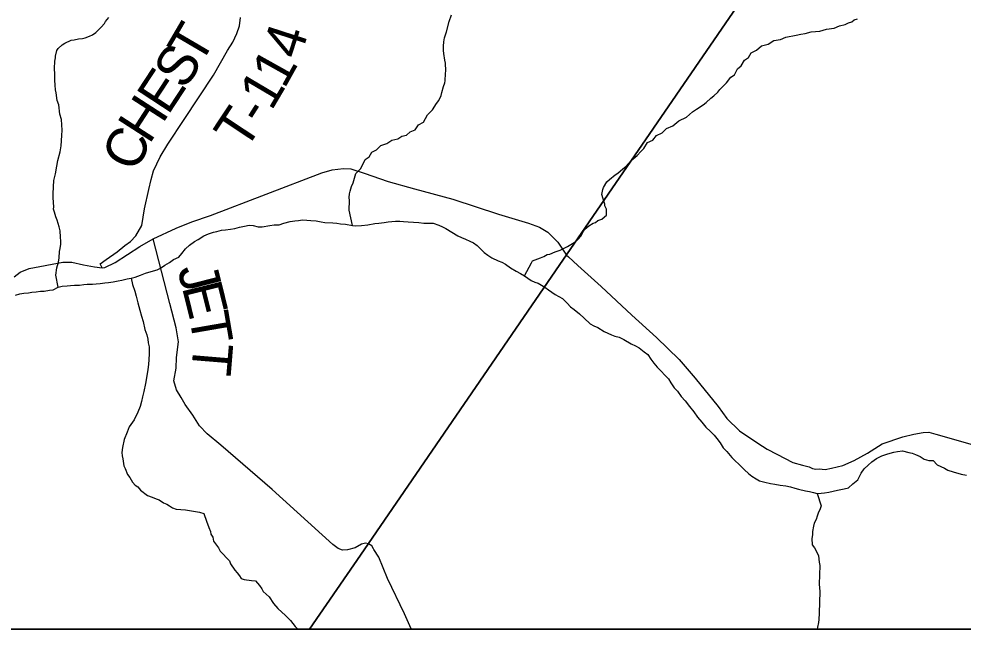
# Model space of a CAD drawing. Extents: x 0 to 39.3, y -3.9 to 22.
# Drawn here: x 3.453 to 4.806, y 13.9 to 14.774 of the extents above; entities that cross this region are included whole.
import ezdxf

# ---------------------------------------------------------------- set-up
doc = ezdxf.new("R2010")
doc.units = 0
for name, color, linetype in [('GM_X_Corporation', 7, 'Continuous'), ('GM_X_County_Road', 7, 'Continuous'), ('GM_X_County_Road_Text', 7, 'Continuous'), ('GM_X_Minor_River', 7, 'Continuous'), ('GM_X_Township_Road', 7, 'Continuous'), ('GM_X_Township_Road_Text', 7, 'Continuous'), ('SH_Data', 7, 'Continuous')]:
    doc.layers.add(name, color=color, linetype=linetype)

msp = doc.modelspace()

# ---------------------------------------------------------------- linework, layer by layer
at = {"layer": 'GM_X_Corporation'}
for points in [[(6.2667, 17.3782), (6.0256, 17.0319), (5.8398, 16.7652), (5.744, 16.6289), (5.7424, 16.6266), (5.2028, 15.8376), (5.0728, 15.652), (4.2376, 14.4362), (4.2334, 14.4302), (3.9536, 14.0228), (3.9474, 14.0138), (3.8692, 13.9), (7.894, 13.9)], [(1.9, 13.9), (3.8692, 13.9), (3.9474, 14.0138), (3.9536, 14.0228), (4.2334, 14.4302), (4.2376, 14.4362), (5.0728, 15.652)]]:
    msp.add_lwpolyline(points, dxfattribs=at)
at = {"layer": 'GM_X_County_Road'}
for points in [[(3.645, 14.4589), (3.6782, 14.4744), (3.7004, 14.4833), (3.7272, 14.4926), (3.887, 14.5537), (3.9018, 14.558), (3.9181, 14.5597), (3.9285, 14.5594), (3.9478, 14.553), (3.9821, 14.5412), (4.0196, 14.5307), (4.0745, 14.5158), (4.1401, 14.4943), (4.1829, 14.4816), (4.1988, 14.476), (4.2108, 14.4685), (4.2253, 14.4544), (4.2378, 14.4357), (4.2406, 14.4331)], [(3.572, 14.4178), (3.5761, 14.418), (3.5907, 14.4252), (3.6262, 14.4482), (3.645, 14.4589)], [(3.9611, 14.0149), (3.9585, 14.0191), (3.9538, 14.0222), (3.9494, 14.023), (3.9438, 14.0215), (3.9347, 14.0165), (3.9239, 14.0136), (3.9164, 14.013), (3.9101, 14.0156), (3.9025, 14.0212), (3.8156, 14.1), (3.7424, 14.1635), (3.7226, 14.1797), (3.7117, 14.191), (3.7021, 14.2066), (3.6911, 14.2218), (3.6855, 14.2317), (3.6788, 14.2426), (3.6749, 14.2557), (3.6781, 14.2738), (3.6788, 14.2889), (3.6813, 14.3116), (3.6781, 14.3314), (3.6689, 14.3664), (3.645, 14.4589)], [(3.4461, 14.4047), (3.4546, 14.4114), (3.4674, 14.4164), (3.5156, 14.4258), (3.5288, 14.4255), (3.5454, 14.4221), (3.5613, 14.4189), (3.572, 14.4178)], [(4.2406, 14.4331), (4.2539, 14.4208), (4.2871, 14.3908), (4.3313, 14.3498), (4.3667, 14.3179), (4.3992, 14.2861), (4.4218, 14.2593), (4.4547, 14.219), (4.4672, 14.2016), (4.4857, 14.184), (4.512, 14.1666), (4.5252, 14.1579), (4.5392, 14.1504), (4.5621, 14.1388), (4.576, 14.1351), (4.5852, 14.1323), (4.5903, 14.1303), (4.5949, 14.1289), (4.5995, 14.1294), (4.6083, 14.1287), (4.6175, 14.1305), (4.6334, 14.1342), (4.6499, 14.1415), (4.6691, 14.1522), (4.69, 14.1652), (4.7195, 14.1753), (4.7351, 14.1794), (4.7485, 14.1818), (4.7569, 14.1821), (4.7667, 14.1795), (4.7922, 14.172), (4.8202, 14.1642)], [(4.0152, 13.9), (4.015, 13.9005), (4.0055, 13.9219), (3.981, 13.9726), (3.9687, 14.003), (3.9616, 14.0141), (3.9611, 14.0149)]]:
    msp.add_lwpolyline(points, dxfattribs=at)
at = {"layer": 'GM_X_Minor_River'}
for points in [[(3.9309, 14.4782), (3.9259, 14.5003), (3.9265, 14.5139), (3.9262, 14.5181), (3.9267, 14.5238), (3.9275, 14.5276), (3.9296, 14.5341), (3.9316, 14.5394), (3.9356, 14.5526), (3.943, 14.5601), (3.9489, 14.5726), (3.9547, 14.5766), (3.9586, 14.5834), (3.9652, 14.5867), (3.9714, 14.5927), (3.9802, 14.5956), (3.9871, 14.6005), (3.9959, 14.6022), (4.0017, 14.6063), (4.0085, 14.6077), (4.0136, 14.6122), (4.0205, 14.6151), (4.0256, 14.6223), (4.0325, 14.6263), (4.0384, 14.6369), (4.0454, 14.644), (4.0512, 14.653), (4.0544, 14.6575), (4.0579, 14.6643), (4.0591, 14.6689), (4.0612, 14.6772), (4.0632, 14.6825), (4.0636, 14.6856), (4.0642, 14.6958), (4.0646, 14.6996), (4.0641, 14.7107), (4.063, 14.7149), (4.0617, 14.7248), (4.0614, 14.729), (4.0611, 14.7351), (4.062, 14.7415), (4.0625, 14.7469), (4.0657, 14.7559), (4.0694, 14.7707), (4.0726, 14.7798)], [(3.509, 14.39), (3.5059, 14.407), (3.5072, 14.4176), (3.5096, 14.4259), (3.5105, 14.432), (3.511, 14.4408), (3.5119, 14.4453), (3.5128, 14.4514), (3.5128, 14.4559), (3.5126, 14.4617), (3.512, 14.4704), (3.5105, 14.4762), (3.5077, 14.4857), (3.5059, 14.4907), (3.5037, 14.4972), (3.5026, 14.5018), (3.5027, 14.5048), (3.5018, 14.5178), (3.5019, 14.5243), (3.503, 14.5429), (3.5054, 14.552), (3.5072, 14.5634), (3.5088, 14.5714), (3.5121, 14.5839), (3.5134, 14.5922), (3.5144, 14.607), (3.5146, 14.6146), (3.5137, 14.6299), (3.5116, 14.6375), (3.5099, 14.6513), (3.5077, 14.6574), (3.5064, 14.6681), (3.505, 14.6727), (3.5047, 14.6795), (3.5041, 14.6864), (3.5042, 14.6948), (3.504, 14.7031), (3.5042, 14.7138), (3.505, 14.7183), (3.5051, 14.721), (3.5071, 14.729), (3.5091, 14.7316), (3.5149, 14.7372), (3.5187, 14.7394), (3.5279, 14.7435), (3.5318, 14.7442), (3.5383, 14.7456), (3.544, 14.7462), (3.5478, 14.7473), (3.5539, 14.7495), (3.5582, 14.7513), (3.5632, 14.7547), (3.5655, 14.7573), (3.5705, 14.7625), (3.5756, 14.7678), (3.5768, 14.7704), (3.5818, 14.776)], [(4.1772, 14.406), (4.1872, 14.4248), (4.1888, 14.4278), (4.2003, 14.4318), (4.2053, 14.434), (4.2099, 14.4366), (4.2137, 14.4373), (4.2214, 14.4406), (4.2287, 14.4431), (4.2391, 14.4483), (4.2437, 14.4509), (4.251, 14.4553), (4.2545, 14.4587), (4.2584, 14.4635), (4.2611, 14.4688), (4.2639, 14.473), (4.2697, 14.4778), (4.2758, 14.4815), (4.2789, 14.4826), (4.2824, 14.4856), (4.2881, 14.4874), (4.292, 14.4908), (4.2947, 14.493), (4.2948, 14.5014), (4.2926, 14.5064), (4.2927, 14.509), (4.2901, 14.5163), (4.2884, 14.5224), (4.2896, 14.53), (4.2908, 14.5326), (4.2955, 14.5409), (4.2994, 14.5439), (4.3075, 14.551), (4.311, 14.5532), (4.3183, 14.5596), (4.3226, 14.5626), (4.33, 14.5712), (4.3389, 14.5786), (4.3439, 14.5843), (4.3482, 14.5884), (4.3537, 14.597), (4.3613, 14.6007), (4.3664, 14.6071), (4.3745, 14.6108), (4.381, 14.6171), (4.3899, 14.6208), (4.3984, 14.6282), (4.4095, 14.6334), (4.418, 14.6409), (4.4238, 14.6449), (4.4334, 14.6509), (4.4377, 14.6542), (4.4446, 14.6606), (4.4485, 14.6639), (4.4543, 14.6692), (4.4574, 14.6729), (4.4632, 14.6789), (4.4667, 14.6827), (4.473, 14.6905), (4.4784, 14.6943), (4.4827, 14.7029), (4.4881, 14.707), (4.4928, 14.7153), (4.4982, 14.719), (4.5022, 14.7254), (4.5098, 14.7295), (4.5168, 14.7358), (4.5264, 14.738), (4.5348, 14.7431), (4.5444, 14.7449), (4.5517, 14.7482), (4.5666, 14.751), (4.5734, 14.7524), (4.5796, 14.7534), (4.5884, 14.7559), (4.6005, 14.7565), (4.6101, 14.7597), (4.6212, 14.7611), (4.6289, 14.7644), (4.6369, 14.7661), (4.6415, 14.7687), (4.6465, 14.7702), (4.6499, 14.7728), (4.6545, 14.7742)], [(3.6272, 14.4073), (3.6344, 14.4099), (3.6458, 14.4131), (3.6508, 14.4145), (3.6558, 14.4171), (3.6619, 14.4216), (3.6684, 14.4253), (3.6745, 14.4293), (3.6818, 14.433), (3.6861, 14.4383), (3.6915, 14.445), (3.6973, 14.4499), (3.7045, 14.4554), (3.7099, 14.4584), (3.7176, 14.4632), (3.7244, 14.4665), (3.7317, 14.4687), (3.7366, 14.4697), (3.7431, 14.4715), (3.7488, 14.4722), (3.756, 14.4732), (3.7621, 14.4738), (3.769, 14.476), (3.7762, 14.4774), (3.7827, 14.4788), (3.7883, 14.478), (3.7955, 14.4763), (3.8016, 14.4762), (3.8126, 14.4783), (3.8187, 14.479), (3.8259, 14.4792), (3.8324, 14.4814), (3.8415, 14.4839), (3.8483, 14.4849), (3.8537, 14.4856), (3.8594, 14.4862), (3.8654, 14.4858), (3.8711, 14.4853), (3.879, 14.4848), (3.8858, 14.4835), (3.8911, 14.4823), (3.9029, 14.4821), (3.9086, 14.4816), (3.9135, 14.4808), (3.921, 14.4799), (3.9309, 14.4782), (3.9358, 14.4777), (3.9438, 14.4784), (3.9529, 14.4793), (3.9628, 14.4811), (3.9685, 14.4817), (3.9761, 14.4824), (3.9818, 14.4834), (3.9871, 14.4841), (3.9924, 14.4844), (3.9988, 14.4846), (4.0041, 14.4838), (4.0106, 14.4833), (4.0185, 14.4828), (4.0257, 14.4827), (4.0333, 14.4818), (4.0394, 14.4817), (4.0466, 14.4816), (4.0545, 14.4788), (4.0597, 14.4764), (4.0646, 14.474), (4.0732, 14.4686), (4.0819, 14.4635), (4.0872, 14.4611), (4.0928, 14.4587), (4.0992, 14.4556), (4.1045, 14.4532), (4.1097, 14.4497), (4.1149, 14.4443), (4.1198, 14.4397), (4.1246, 14.4358), (4.1306, 14.4319), (4.1397, 14.4275), (4.1449, 14.4255), (4.1502, 14.4228), (4.1573, 14.4174), (4.1656, 14.413), (4.1716, 14.4095), (4.1772, 14.406), (4.187, 14.3994), (4.1922, 14.397), (4.1971, 14.3958), (4.2065, 14.3899), (4.2118, 14.386), (4.2166, 14.3825), (4.2215, 14.3794), (4.2268, 14.3763), (4.232, 14.3735), (4.2387, 14.367), (4.2432, 14.3619), (4.2484, 14.3577), (4.2563, 14.3518), (4.263, 14.3456), (4.2716, 14.3375), (4.2769, 14.3344), (4.2825, 14.332)], [(3.4477, 14.3784), (3.4542, 14.3802), (3.4599, 14.3813), (3.4664, 14.3819), (3.4713, 14.3826), (3.4774, 14.3833), (3.4835, 14.3843), (3.4892, 14.3842), (3.4964, 14.3856), (3.5021, 14.3859), (3.509, 14.39), (3.5147, 14.3914), (3.5219, 14.3916), (3.5268, 14.3923), (3.5325, 14.3926), (3.5394, 14.3929), (3.5458, 14.3935), (3.5507, 14.3942), (3.5583, 14.3941), (3.5636, 14.3947), (3.5693, 14.395), (3.5758, 14.396), (3.5811, 14.3967), (3.588, 14.3977), (3.5952, 14.3988), (3.6005, 14.3998), (3.6081, 14.4016), (3.6138, 14.4026), (3.6192, 14.4044), (3.6272, 14.4073)], [(3.6138, 14.4026), (3.6155, 14.3936), (3.6189, 14.3841), (3.6207, 14.3768), (3.6232, 14.3673), (3.626, 14.3569), (3.6285, 14.3485), (3.631, 14.3405), (3.6335, 14.329), (3.636, 14.3214), (3.6374, 14.3153), (3.6381, 14.3103), (3.6395, 14.3042), (3.6393, 14.2943), (3.6388, 14.2863), (3.6383, 14.2791), (3.6374, 14.2719), (3.6361, 14.2628), (3.634, 14.2521), (3.6319, 14.2404), (3.6299, 14.2328), (3.6286, 14.2263), (3.6266, 14.2191), (3.623, 14.2108), (3.6178, 14.1999), (3.6108, 14.1897), (3.608, 14.1822), (3.6036, 14.1716), (3.6011, 14.1602), (3.6002, 14.153), (3.6009, 14.148), (3.6016, 14.1438), (3.6033, 14.1339), (3.6052, 14.1301), (3.6084, 14.1216), (3.6118, 14.117), (3.6158, 14.1105), (3.6196, 14.1062), (3.6233, 14.1039), (3.6271, 14.0989), (3.6372, 14.0914), (3.644, 14.089), (3.6497, 14.0867), (3.6538, 14.0851), (3.6598, 14.0808), (3.6648, 14.0792), (3.6685, 14.0765), (3.673, 14.0737), (3.6783, 14.0717), (3.6916, 14.0707), (3.7057, 14.0686), (3.7114, 14.0673), (3.7178, 14.0657), (3.7218, 14.0546), (3.7251, 14.0458), (3.7276, 14.04), (3.7279, 14.0358), (3.7305, 14.0316), (3.7319, 14.0259), (3.739, 14.0166), (3.7412, 14.0116), (3.7546, 13.9977), (3.7561, 13.9935), (3.7624, 13.9846), (3.7654, 13.9808), (3.7687, 13.9762), (3.7713, 13.9723), (3.7755, 13.9711), (3.7861, 13.9698), (3.7918, 13.9693), (3.7978, 13.9627), (3.8007, 13.9577), (3.803, 13.9539), (3.8116, 13.9461), (3.8175, 13.9369), (3.8238, 13.9295), (3.8295, 13.9245), (3.8343, 13.9202), (3.8422, 13.9121), (3.8485, 13.9036), (3.8523, 13.9)], [(4.2825, 14.332), (4.2915, 14.3262), (4.2968, 14.3238), (4.302, 14.3218), (4.3069, 14.3198), (4.313, 14.3182), (4.3197, 14.3147), (4.3303, 14.3088), (4.3366, 14.3056), (4.3419, 14.3029), (4.349, 14.2974), (4.3539, 14.2932), (4.3583, 14.2866), (4.3628, 14.2809), (4.3676, 14.2751), (4.3732, 14.2697), (4.3784, 14.2639), (4.3836, 14.2585), (4.3869, 14.2527), (4.3917, 14.2458), (4.3966, 14.2411), (4.4021, 14.2331), (4.4074, 14.2269), (4.414, 14.2188), (4.42, 14.2111), (4.4255, 14.2038), (4.4315, 14.1965), (4.4374, 14.1895), (4.4441, 14.183), (4.449, 14.1779), (4.4531, 14.1729), (4.4579, 14.1668), (4.4623, 14.1599), (4.4672, 14.1545), (4.4746, 14.146), (4.4795, 14.1409), (4.4843, 14.1363), (4.4925, 14.1282), (4.4985, 14.1228), (4.5034, 14.1189), (4.5094, 14.1154), (4.5142, 14.1126), (4.5218, 14.1106), (4.5297, 14.1086), (4.5361, 14.1077), (4.5437, 14.1064), (4.552, 14.1051), (4.5588, 14.1039), (4.5649, 14.1019), (4.5701, 14.1006), (4.5803, 14.0982), (4.5856, 14.0973), (4.5917, 14.0957), (4.597, 14.0945), (4.6023, 14.0948), (4.6072, 14.0951), (4.6137, 14.0961), (4.6258, 14.0989), (4.6357, 14.1011), (4.6418, 14.1025), (4.648, 14.1081), (4.6549, 14.114), (4.66, 14.1235), (4.6643, 14.1298), (4.67, 14.1347), (4.675, 14.1395), (4.6816, 14.1444), (4.6896, 14.1484), (4.6965, 14.1506), (4.7014, 14.152), (4.7067, 14.1534), (4.7121, 14.1545), (4.7189, 14.1555), (4.728, 14.1531), (4.7329, 14.1522), (4.7378, 14.1503), (4.7442, 14.1471), (4.7502, 14.1436), (4.757, 14.1416), (4.763, 14.1415)], [(4.763, 14.1415), (4.7686, 14.1353), (4.7791, 14.1306), (4.784, 14.1278), (4.7919, 14.1254), (4.8033, 14.1222), (4.8108, 14.1205)], [(4.597, 14.0945), (4.6027, 14.0768), (4.6011, 14.0723), (4.5983, 14.0662), (4.5967, 14.0617), (4.5955, 14.0572), (4.5927, 14.0519), (4.5915, 14.0473), (4.5902, 14.0397), (4.5901, 14.0352), (4.5893, 14.0299), (4.5898, 14.0207), (4.5932, 14.0165), (4.5965, 14.01), (4.5987, 14.005), (4.5997, 13.9958), (4.6004, 13.9912), (4.5999, 13.9646), (4.6004, 13.9539), (4.5999, 13.9227), (4.599, 13.914), (4.5985, 13.9094), (4.5972, 13.9026), (4.5967, 13.9)]]:
    msp.add_lwpolyline(points, dxfattribs=at)
at = {"layer": 'GM_X_Township_Road'}
msp.add_lwpolyline([(3.572, 14.4178), (3.5691, 14.4235), (3.578, 14.4294), (3.5934, 14.4407), (3.6047, 14.4496), (3.6127, 14.4555), (3.6203, 14.4635), (3.6289, 14.4783), (3.6329, 14.5022), (3.6389, 14.53), (3.6425, 14.5442), (3.6459, 14.5566), (3.6551, 14.5766), (3.6663, 14.5948), (3.6897, 14.6302), (3.7317, 14.6934), (3.7516, 14.7288), (3.7592, 14.7407), (3.7652, 14.7531), (3.769, 14.7645), (3.7704, 14.7763)], dxfattribs=at)
at = {"layer": 'SH_Data'}
msp.add_lwpolyline([(1.9, 21.1), (9.1, 21.1), (9.1, 13.9), (1.9, 13.9)], close=True, dxfattribs=at)

# ---------------------------------------------------------------- texts
at = {"layer": 'GM_X_County_Road_Text'}
for s, rotation, p in [('J', 284.1804, (3.6797, 14.416)), ('E', 283.9942, (3.6862, 14.3902)), ('T', 279.7973, (3.6963, 14.3501)), ('T', 265.2762, (3.7034, 14.312))]:
    msp.add_text(s, height=0.0568, rotation=rotation, dxfattribs=at).set_placement(p)
at = {"layer": 'GM_X_Township_Road_Text'}
for s, rotation, p in [('T', 59.6113, (3.7122, 14.7055)), ('4', 72.0615, (3.855, 14.7143)), ('S', 57.3036, (3.6902, 14.6711)), ('1', 60.824, (3.8331, 14.6727)), ('E', 56.7259, (3.6665, 14.6351)), ('1', 59.417, (3.8146, 14.6412)), ('H', 57.1404, (3.6395, 14.5932)), ('T', 56.4383, (3.7768, 14.5834)), ('-', 57.4736, (3.8009, 14.6197)), ('C', 65.6496, (3.6213, 14.5526))]:
    msp.add_text(s, height=0.0568, rotation=rotation, dxfattribs=at).set_placement(p)

doc.saveas('drawing.dxf')
